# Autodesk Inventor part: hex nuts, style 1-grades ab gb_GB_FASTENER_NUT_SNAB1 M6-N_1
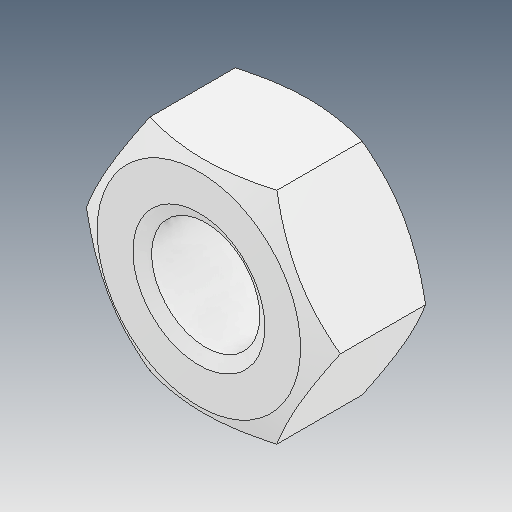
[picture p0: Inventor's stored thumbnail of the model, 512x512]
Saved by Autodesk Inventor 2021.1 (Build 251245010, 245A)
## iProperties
Created: 2021-05
Part Number: hex nuts, style 1-grades ab gb_GB_FASTENER_NUT_SNAB1 M6-N_1
Material: Ogólny
Document SubType Name: Modeling
Designer: user
Density: 1 g/cm^3
Appearance: Domyślna
Author: user
Revision Number: ÈÎºÎ
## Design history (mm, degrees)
feature "ÊäÈë1"
node "Bryła1"
